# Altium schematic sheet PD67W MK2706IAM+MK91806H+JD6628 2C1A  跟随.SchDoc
size 330 x 549 mm
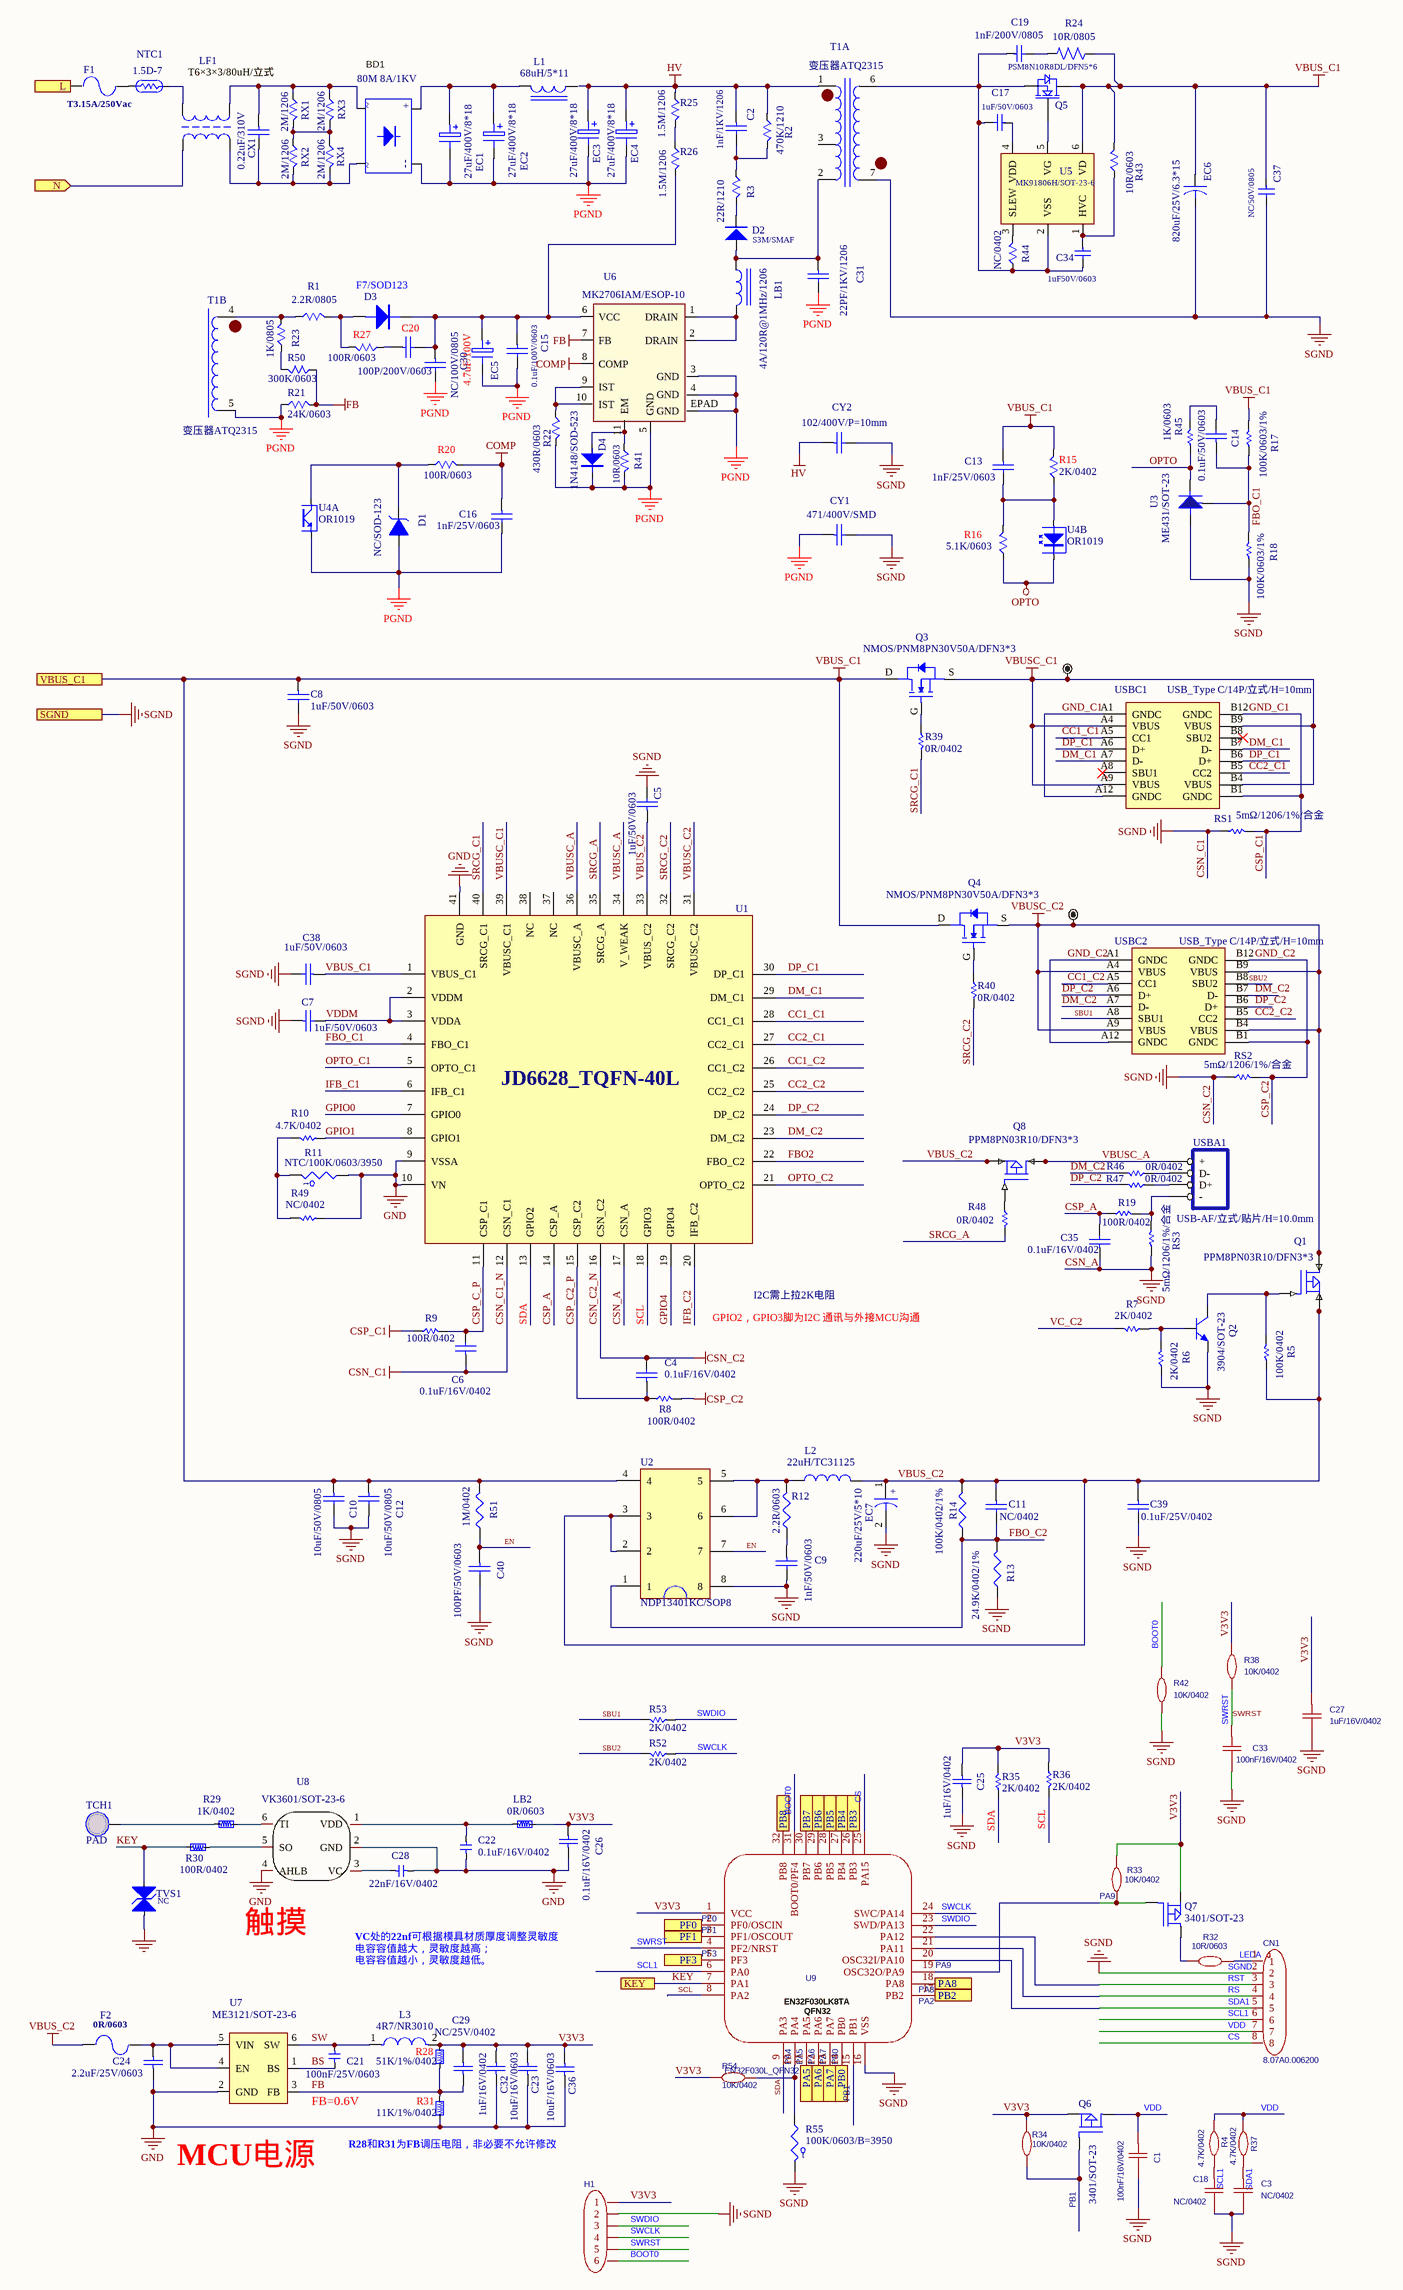
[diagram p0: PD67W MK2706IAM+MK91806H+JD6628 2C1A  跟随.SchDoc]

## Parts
BD1  80M 8A/1KV  [BD_ABS-6-2]
C1  100nF/16V/0402  [0402C]
C2  1nF/1KV/1206  [C1206-t]
C3  NC/0402  [0402C]
C4  0.1uF/16V/0402  [C0603]
C5  1uF/50V/0603  [C0805]
C6  0.1uF/16V/0402  [C0603]
C7  1uF/50V/0603  [C0603]
C8  1uF/50V/0603  [C0805]
C9  1nF/50V/0603  [C0603]
C10  10uF/50V/0805  [C0603]
C11  NC/0402  [C0603]
C12  10uF/50V/0805  [C0603]
C13  1nF/25V/0603  [C0603-T]
C14  0.1uF/50V/0603  [C0805]
C15  0.1uF/100V/0603  [C0603-T]
C16  1nF/25V/0603  [C0603-T]
C17  1uF/50V/0603  [C0603-S]
C18  NC/0402  [0402C]
C19  1nF/200V/0805  [C0805]
C20  100P/200V/0603  [C1206-t]
C21  100nF/25V/0603  [0402C]
C22  0.1uF/16V/0402  [0402C]
C23  10uF/16V/0603  [0805C]
C24  2.2uF/25V/0603  [0805C]
C25  1uF/16V/0402  [0805C]
C26  0.1uF/16V/0402  [0805C]
C27  1uF/16V/0402  [0402C]
C28  22nF/16V/0402  [0402C]
C29  NC/25V/0402  [0805C]
C30  NC/100V/0805  [C0603-T]
C31  22PF/1KV/1206  [C1206-t]
C32  1uF/16V/0402  [0805C]
C33  100nF/16V/0402  [0402C]
C34  1uF50V/0603  [C0603-S]
C35  0.1uF/16V/0402  [C0603]
C36  10uF/16V/0603  [0805C]
C37  NC/50V/0805  [C0603-S]
C38  1uF/50V/0603  [C0805]
C39  0.1uF/25V/0402  [C0603]
C40  100PF/50V/0603  [C0603]
CN1  8.07A0.006200  [DIP8]
CX1  0.22uF/310V  [CX6*12]
CY1  471/400V/SMD  [C1206-t]
CY2  102/400V/P=10mm  [C1206-t]
D1  NC/SOD-123  [SOD-523-T]
D2  S3M/SMAF  [D(SMA)-t]
D3  F7/SOD123  [D-SOD123]
D4  1N4148/SOD-523  [DO-201]
EC1  27uF/400V/8*18  [CEV10]
EC2  27uF/400V/8*18  [CEV10]
EC3  27uF/400V/8*18  [CEV8]
EC4  27uF/400V/8*18  [CEV8]
EC5  4.7uF/100V  [CEV5]
EC6  820uF/25V/6.3*15  [CE6.3X15]
EC7  220uF/25V/5*10  [CE-D8-P3.5]
F1  T3.15A/250Vac  [FUSE4X8]
F2  0R/0603  [FUSE4X8]
H1  (no value)  [SO-8S]
L1  68uH/5*11  [L-6.5MAX-P2.5]
L2  22uH/TC31125  [IND\AMPI0630\5.9MM(DIP+SMD)]
L3  4R7/NR3010  [L4*4]
LB1  4A/120R@1MHz/1206  [L-6.5MAX-P2.5]
LB2  0R/0603  [0402R]
LF1  T6×3×3/80uH/立式  [L12.7×7.9×4]
NTC1  1.5D-7  [5D-5]
Q1  PPM8PN03R10/DFN3*3
Q2  3904/SOT-23  [SOT-23]
Q3  NMOS/PNM8PN30V50A/DFN3*3  [MOS\DFN-8(3x3)]
Q4  NMOS/PNM8PN30V50A/DFN3*3  [MOS\DFN-8(3x3)]
Q5  PSM8N10R8DL/DFN5*6
Q6  3401/SOT-23  [SOT-23]
Q7  3401/SOT-23  [SOT-23]
Q8  PPM8PN03R10/DFN3*3
R1  2.2R/0805  [R0603-T]
R2  470K/1210  [R1206-T]
R3  22R/1210  [R1206-T]
R4  4.7K/0402  [0402R]
R5  100K/0402  [R0603]
R6  2K/0402  [R0603]
R7  2K/0402  [R0603]
R8  100R/0402  [R0603]
R9  100R/0402  [R0603]
R10  4.7K/0402  [R0603]
R11  NTC/100K/0603/3950  [SIP2-2.5]
R12  2.2R/0603  [R0603]
R13  24.9K/0402/1%  [R0603]
R14  100K/0402/1%  [R0603]
R15  2K/0402  [R0603-T]
R16  5.1K/0603  [R0603-T]
R17  100K/0603/1%  [R0603]
R18  100K/0603/1%  [R0603]
R19  100R/0402  [R0603]
R20  100R/0603  [R0603-T]
R21  24K/0603  [R0603-T]
R22  430R/0603  [R0603-T]
R23  1K/0805  [R0603-T]
R24  10R/0805  [R1206-T]
R25  1.5M/1206  [R0603-T]
R26  1.5M/1206  [R0603-T]
R27  100R/0603  [R0603-T]
R28  51K/1%/0402  [0402R]
R29  1K/0402  [0402R]
R30  100R/0402  [0402R]
R31  11K/1%/0402  [0402R]
R32  10R/0603  [0603RX]
R33  10K/0402  [0402R]
R34  10K/0402  [0402R]
R35  2K/0402  [R0603]
R36  2K/0402  [R0603]
R37  4.7K/0402  [0402R]
R38  10K/0402  [0402R]
R39  0R/0402  [R0603]
R40  0R/0402  [R0603]
R41  10R/0603  [R0603-T]
R42  10K/0402  [0402R]
R43  10R/0603  [R1206-T]
R44  NC/0402  [R1206-T]
R45  1K/0603  [R0603]
R46  0R/0402  [R0603]
R47  0R/0402  [R0603]
R48  0R/0402  [R0603]
R49  NC/0402  [R0603]
R50  300K/0603  [R0603-T]
R51  1M/0402  [R0603]
R52  2K/0402  [R0603]
R53  2K/0402  [R0603]
R54  10K/0402  [0402R]
R55  100K/0603/B=3950  [SIP2-2.5]
RS1  5mΩ/1206/1%/合金  [1206]
RS2  5mΩ/1206/1%/合金  [1206]
RS3  5mΩ/1206/1%/合金  [1206]
RX1  2M/1206  [R1206-T]
RX2  2M/1206  [R1206-T]
RX3  2M/1206  [R1206-T]
RX4  2M/1206  [R1206-T]
T1  变压器ATQ2315  [ATQ17-13]  (parts A,B of 2)
TCH1  PAD  [1PIN]
TVS1  NC  [DFN1006-2L]
U1  JD6628_TQFN-40L  [IC\QFN-40\0.4mm\5x5mm]
U2  NDP13401KC/SOP8  [DIP8]
U3  ME431/SOT-23  [SOT-23]
U4  OR1019  [CT1018]  (parts A,B of 2)
U5  MK91806H/SOT-23-6
U6  MK2706IAM/ESOP-10  [SO-10]
U7  ME3121/SOT-23-6  [SOT-23-6]
U8  VK3601/SOT-23-6  [SOT-23-6]
U9  EN32F030L_QFN32  [QFN32 4*4]
USBA1  USB-AF/立式/贴片/H=10.0mm  [USB 10.0H]
USBC1  USB_Type C/14P/立式/H=10mm  [USB_SBC-160S1-20-S235]
USBC2  USB_Type C/14P/立式/H=10mm  [USB_SBC-160S1-20-S235]
VBUSC_C1  TP\H50MIL  [TP\H50MIL]  (value not drawn)
VBUSC_C2  TP\H50MIL  [TP\H50MIL]  (value not drawn)

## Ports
KEY, L (in), N (in), PA5 (in), PA6 (in), PA7 (in), PA8 (in), PB0 (in), PB2 (in), PB3 (in), PB4 (in), PB5 (in), PB6 (in), PB7 (in), PB8 (in), PF0 (in), PF1 (in), PF3 (in), SGND, VBUS_C1

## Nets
COMP: C16.1 R20.2 U6.8(COMP)
CSN_A: C1.1 C3.1 C4.2 C5.2 C6.1 C7.1 C8.2 C9.2 C10.2 C12.2 C18.1 C25.1 C27.1 C33.1 C35.1 C37.2 C38.2 C39.2 C40.2 CN1.2 CY1.2 CY2.2 EC6.2 EC7.2 H1.2 Q2.2(E) R6.1 R13.1 R18.1 R42.1 R55.2 RS1.1 RS2.1 RS3.1 T1.7 U1.12(CSN_C1) U1.16(CSN_C2) U1.17(CSN_A) U2.8 U3.3 U9.16(VSS) ; port SGND  [also labelled CSN_C1, CSN_C1_N, CSN_C2, CSN_C2_N, SGND]
CSP_C1: R9.1 RS1.2 USBC1.A1(GNDC) USBC1.A12(GNDC) USBC1.B1(GNDC) USBC1.B12(GNDC)  [also labelled GND_C1]
CSP_C2: R8.2 RS2.2 USBC2.A1(GNDC) USBC2.A12(GNDC) USBC2.B1(GNDC) USBC2.B12(GNDC)  [also labelled GND_C2]
FB: C29.1 R21.2 R28.1 R31.2 R50.1 U6.7(FB) U7.3(FB)
GND: C22.2 C23.1 C24.1 C26.1 C28.1 C32.1 C36.1 R11.1 R31.1 R49.1 TVS1.1(A) U1.9(VSSA) U1.10(VN) U1.41(GND) U7.2(GND) U8.2(GND) U8.4(AHLB)
HV: C2.1 CY2.1 EC3.1 EC4.1 R2.1 R25.1 T1.1
OPTO: R16.1 R45.1 U3.2 U4.2(K)
PGND: BD1.2 C15.2 C16.2 C30.2 C31.2 CY1.1 D1.1(A) D4.2(K) EC1.2 EC2.2 EC3.2 EC4.2 EC5.2 R21.1 R22.2 R41.2 T1.5 U4.3(E) U6.3(GND) U6.4(GND) U6.5(GND) U6.EPAD(GND)
VBUS_C1: C8.1 C10.1 C12.1 C13.1 C37.1 C38.1 EC6.1 Q3.D Q4.D Q5.?2 R15.2 R17.2 R24.1 R43.2 R51.2 U1.1(VBUS_C1) U2.4 U5.6(VD) ; port VBUS_C1
VBUS_C2: C5.1 C11.1 C39.1 EC7.1 F2.2 L2.2 Q1.1 Q1.2 Q1.3 Q8.1 Q8.2 Q8.3 R5.1 R14.2 U1.33(VBUS_C2) U2.2 U2.3
VBUSC_C1: Q3.S U1.39(VBUSC_C1) USBC1.A4(VBUS) USBC1.A9(VBUS) USBC1.B4(VBUS) USBC1.B9(VBUS) VBUSC_C1.1
VBUSC_C2: Q1.5 Q1.6 Q1.7 Q1.8 Q4.S U1.31(VBUSC_C2) USBC2.A4(VBUS) USBC2.A9(VBUS) USBC2.B4(VBUS) USBC2.B9(VBUS) VBUSC_C2.1
BOOT0: H1.6 R42.2 U9.31(BOOT0/PF4)
BS: C21.1 U7.1(BS)
CC1_C1: U1.28(CC1_C1) USBC1.A5(CC1)
CC1_C2: U1.26(CC1_C2) USBC2.A5(CC1)
CC2_C1: U1.27(CC2_C1) USBC1.B5(CC2)
CC2_C2: U1.25(CC2_C2) USBC2.B5(CC2)
CS: CN1.8 U9.25(PA15)
CSP_A: C35.2 R19.1 U1.14(CSP_A)
CSP_C2_P: C4.1 R8.1 U1.15(CSP_C2)
CSP_C_P: C6.2 R9.2 U1.11(CSP_C1)
DM_C1: U1.29(DM_C1) USBC1.A7(D-) USBC1.B7(D-)
DM_C2: R46.2 U1.23(DM_C2) USBC2.A7(D-) USBC2.B7(D-)
DP_C1: U1.30(DP_C1) USBC1.A6(D+) USBC1.B6(D+)
DP_C2: R47.2 U1.24(DP_C2) USBC2.A6(D+) USBC2.B6(D+)
EN: C40.1 R51.1 U2.7
FBO2: U1.22(FBO_C2)
FBO_C1: C14.1 R17.1 R18.2 U1.4(FBO_C1) U3.1(R)
FBO_C2: C11.2 R13.2 R14.1 U2.1
GPIO0: U1.7(GPIO0)
GPIO1: R10.1 U1.8(GPIO1)
GPIO4: U1.19(GPIO4)
IFB_C1: U1.6(IFB_C1)
IFB_C2: U1.20(IFB_C2)
KEY: R30.2 TVS1.2(A) U9.7(PA1) ; port KEY
L: F1.2 ; port L
LEDA: CN1.1 R32.2
N: LF1.3 ; port N
OPTO_C1: U1.5(OPTO_C1)
OPTO_C2: U1.21(OPTO_C2)
PA2: U9.17(PB2) ; port PB2
PA4: R54.2 R55.1 U9.10(PA4)
PA5: U9.11(PA5) ; port PA5
PA6: U9.12(PA6) ; port PA6
PA7: U9.13(PA7) ; port PA7
PA8: U9.18(PA8) ; port PA8
PA9: Q7.1(G) R33.2 U9.19(OSC32O/PA9)
PB0: U9.14(PB0) ; port PB0
PB1: Q6.1(G) R34.2 U9.15(PB1)
PB3: U9.26(PB3) ; port PB3
PB4: U9.27(PB4) ; port PB4
PB5: U9.28(PB5) ; port PB5
PB6: U9.29(PB6) ; port PB6
PB7: U9.30(PB7) ; port PB7
PB8: U9.32(PB8) ; port PB8
PF0: U9.2(PF0/OSCIN) ; port PF0
PF1: U9.3(PF1/OSCOUT) ; port PF1
PF3: U9.5(PF3) ; port PF3
RS: CN1.4 U9.21(PA11)
RST: CN1.3 U9.22(PA12)
SBU1: R53.2 USBC2.A8(SBU1)
SBU2: R52.2 USBC2.B8(SBU2)
SCL: R36.2 U1.18(GPIO3) U9.8(PA2)
SCL1: C18.2 CN1.6 R4.2 U9.6(PA0)
SDA: R35.1 U1.13(GPIO2) U9.9(PA3)
SDA1: C3.2 CN1.5 R37.2 U9.20(OSC32I/PA10)
SRCG_A: R48.2 U1.35(SRCG_A)
SRCG_C1: R39.2 U1.40(SRCG_C1)
SRCG_C2: R40.2 U1.32(SRCG_C2)
SW: C21.2 L3.1 U7.6(SW)
SWCLK: H1.4 R52.1 U9.24(SWC/PA14)
SWDIO: H1.3 R53.1 U9.23(SWD/PA13)
SWRST: C33.2 H1.5 R38.1 U9.4(PF2/NRST)
V3V3: C23.2 C25.2 C26.2 C27.2 C29.2 C32.2 C36.2 H1.1 L3.2 LB2.2 Q6.2(S) Q7.2(S) R28.2 R33.1 R34.1 R35.2 R36.1 R38.2 R54.1 U9.1(VCC)
VBUSC_A: Q8.5 Q8.6 Q8.7 Q8.8 U1.34(V_WEAK) U1.36(VBUSC_A) USBA1.+
VC_C2: R7.2
VDD: C1.2 CN1.7 Q6.3(D) R4.1 R37.1
VDDM: C7.2 U1.2(VDDM) U1.3(VDDA)
NetBD1_1: BD1.1 EC1.1 EC2.1 L1.2
NetBD1_3: BD1.3 CX1.2 LF1.4 RX2.2 RX4.2
NetBD1_4: BD1.4 CX1.1 LF1.1 RX1.1 RX3.1
NetC2_2: C2.2 R2.2 R3.1
NetC9_1: C9.1 R12.1
NetC13_2: C13.2 R15.1 R16.2 U4.1(A)
NetC14_2: C14.2 R45.2
NetC15_1: C15.1 C20.2 C30.1 D3.2 EC5.1 R26.2 U6.6(VCC)
NetC17_1: C17.1 U5.4(VDD)
NetC17_2: C17.2 C19.1 C34.2 Q5.?3 R44.1 T1.6 U5.2(VSS)
NetC19_2: C19.2 R24.2
NetC20_1: C20.1 R27.1
NetC22_1: C22.1 LB2.1 U8.1(VDD)
NetC24_2: C24.2 F2.1 U7.4(EN) U7.5(VIN)
NetC28_2: C28.2 U8.3(VC)
NetC31_1: C31.1 D2.A LB1.1 T1.2
NetC34_1: C34.1 R43.1 U5.1(HVC)
NetD1_2: D1.2(K) R20.1 U4.4(C)
NetD2_K: D2.K R3.2
NetD3_1: D3.1 R1.2 R27.2
NetD4_1: D4.1(A) R41.1 U6.11(EM)
NetF1_1: F1.1 NTC1.1
NetL2_1: L2.1 R12.2 U2.5 U2.6
NetLB1_2: LB1.2 U6.1(DRAIN) U6.2(DRAIN)
NetLF1_2: LF1.2 NTC1.2
NetQ1_4: Q1.4 Q2.3(C) R5.2
NetQ2_1: Q2.1(B) R6.2 R7.1
NetQ3_G: Q3.G R39.1
NetQ4_G: Q4.G R40.1
NetQ5_?1: Q5.?1 U5.5(VG)
NetQ7_3: Q7.3(D) R32.1
NetQ8_4: Q8.4 R48.1
NetR1_1: R1.1 R23.2 T1.4
NetR10_2: R10.2 R11.2 R49.2
NetR19_2: R19.2 RS3.2 USBA1.-
NetR22_1: R22.1 U6.9(IST) U6.10(IST)
NetR23_1: R23.1 R50.2
NetR25_2: R25.2 R26.1
NetR29_1: R29.1 TCH1.1
NetR29_2: R29.2 U8.6(TI)
NetR30_1: R30.1 U8.5(SO)
NetR44_2: R44.2 U5.3(SLEW)
NetR46_1: R46.1 USBA1.D-
NetR47_1: R47.1 USBA1.D+
NetRX1_2: RX1.2 RX2.1 RX3.2 RX4.1

Not connected (* = marked no-connect by the designer): L1 1; T1 3; U1 37(NC) 38(NC); USBC1 A8(SBU1)* B8(SBU2)*

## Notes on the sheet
- I2C需上拉2K电阻
- GPIO2，GPIO3脚为I2C 通讯与外接MCU沟通
- (near U8) 触摸
- VC处的22nf可根据模具材质厚度调整灵敏度
- 电容容值越大，灵敏度越高；
- 电容容值越小，灵敏度越低。
- FB=0.6V
- MCU电源
- (near R31) R28和R31为FB调压电阻，非必要不允许修改

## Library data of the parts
BD1 = BD2
C1 C3 C18 = CAP_0603: Symbol: Capacitance; Value: 10nF; 3D Model: ac125912035d415993ca9572d50418b1聨0819f05c4eef4c71ace90d822a990e87¦; 3D Model Transform: 62.992,31.496,0,0,0,0,0,0,0; ConvertToPcb: yes; ModelName: C0603_L1.6-W0.8-H0.8
C2 C20 C31 CY1 CY2 = C1206
C4-C8 C14 C35 C38 = CAP
C9-C12 C39 C40 = CAP: Capacitor no polarity
C13 C15 C16 C30 = C0603
C17 C19 C34 C37 = CAPACITOR
C21 C22 C28 = CAP: X7R, 25V, +/-5%
C23 C36 = CAP0603: Capacitor; Value: 0603
C24 C29 = CAP0603: Capacitor; Value: 0805
C25 C26 C32 = CAP0603: Capacitor; Value: 0402
C27 = CAP_0603: Symbol: Capacitance; Value: 1uF; 3D Model: ac125912035d415993ca9572d50418b1聨0819f05c4eef4c71ace90d822a990e87¦; 3D Model Transform: 62.992,31.496,0,0,0,0,0,0,0; ConvertToPcb: yes; ModelName: C0603_L1.6-W0.8-H0.8
C33 = CAP_0603: Symbol: Capacitance; Value: 100nF; 3D Model: ac125912035d415993ca9572d50418b1聨0819f05c4eef4c71ace90d822a990e87¦; 3D Model Transform: 62.992,31.496,0,0,0,0,0,0,0; ConvertToPcb: yes; ModelName: C0603_L1.6-W0.8-H0.8
CN1 = 8.07A0.006200: AddInBom: yes; ModelId: c65f7b8c237e46d0ab01f9c6002df34e聨0819f05c4eef4c71ace90d822a990e87¦; ModelName: FPC-SMD_6P-P0.50_8.07A0.006200; ModelTransform: 196.85,150.89954,0,0,0,0,0,10.039,0
CX1 = CX6*12
D1 = D Zener
D2 = D(SMA)
D3 = D-SOD123: DIODE; Text Field1: D:\DESIGN\LIB\SCHLIB\
D4 = DIODE
EC1 EC2 = CEV10: Text Field1: F:\RD\LIB\SCHLIB\
EC3 EC4 = CEV8: Text Field1: F:\RD\LIB\SCHLIB\
EC5 = CEV5: Text Field1: F:\RD\LIB\SCHLIB\
EC6 = E-CAP
EC7 = CAP POL: Capacitor , have polarity
F1 F2 = FUSE
H1 = HDR-M_2.54_1x6P: Symbol: Header-Male-2.54_1x6; 3D Model: 60739dffc9b04830a286435b0fefbd4a聨0819f05c4eef4c71ace90d822a990e87¦; 3D Model Transform: 599.999,100,0,0,0,0,0,0,-118.11; ConvertToPcb: yes; ModelName: HDR2.54-M-LI-1X6P
L1 LB1 = Inductor Iron
L2 = INDUCTOR
L3 = L
LB2 R28-R31 = RES: 1/8W 5%
LF1 = L12.7×7.9×4
NTC1 = NTC
Q1 Q8 = MOS-P 8PS
Q2 = NPN: NPN Transistor
Q3 Q4 = MOS\NMOS\FKS4004: SOP-8
Q5 = N MOS: 4.2mR/100V
Q6 Q7 = MOSFET P
R1 R15 R16 R20-R23 R25-R27 R41 R50 = R0603
R2 R3 R43 R44 RX1-RX4 = R1206
R4 R32-R34 R37 R38 R42 R54 = Res_0603: 3D Model: fc143cca1e79419f9cd78b61e9279f08聨0819f05c4eef4c71ace90d822a990e87¦; 3D Model Transform: 31.8897,63.7794,0,90,0,0,0,0,0; Value: 10K; ConvertToPcb: yes; ModelName: R0603
R5-R10 R17-R19 R35 R36 R39 R40 R45-R49 R52 R53 RS1-RS3 = RES SMD
R11 R55 = THERMISTOR
R12-R14 R51 = RES
R24 = RESISTOR
T1 = 变压器
TVS1 = DD ZENER
U1 = JD6628_TQFN-40L: TQFN-40L
U2 = DIP8
U3 = 431
U4 = OPTOISO1: Optoisolator
U5 = MP6908
U6 = U-JW1515H
U7 = ME3116
U8 = RH6016C_1: Symbol: 8205-SOT23-6_1; PCB Footprint: ROMOSS_SOT23-6; Add into BOM: yes; Origin Footprint 1: SOT23-6
U9 = EN32F030L_QFN32: 3D Model: 44e82d2ccee74d7b8bf79e386322e8e3聨0819f05c4eef4c71ace90d822a990e87¦; 3D Model Transform: 197.63739924907682,197.63739924907682,33.858198949880894,0,0,0,0,0,0; AddInBom: yes; ModelName: QFN-32_L5.0-W5.0-P0.50-TL-EP2.3
USBA1 = 4 HEADER: 4 Pin Header
USBC1 USBC2 = USB_Type C_FEMALE_16PIN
